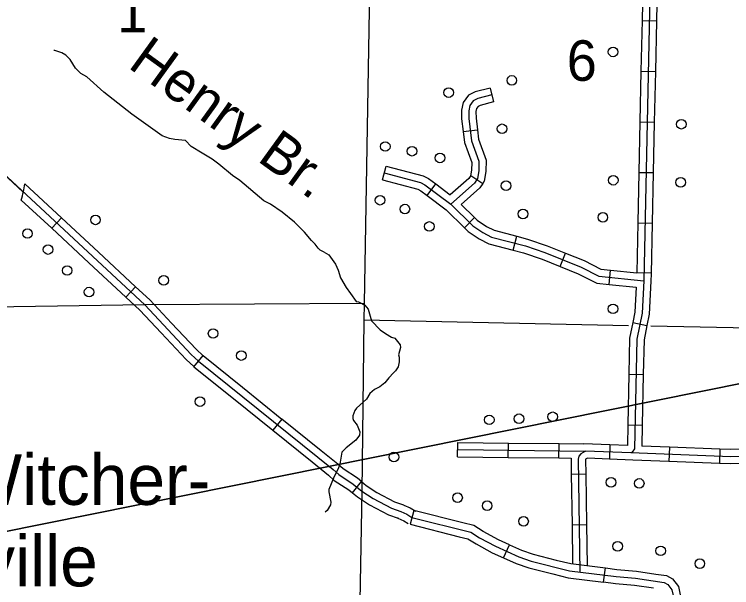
# Model space of a CAD drawing. Extents: x -4786562 to 2097152, y -862751 to 524288.
# Drawn here: x 1377442.5 to 1377649.7, y 379252.8 to 379418.5 of the extents above; entities that cross this region are included whole.
import ezdxf

# ---------------------------------------------------------------- set-up
doc = ezdxf.new("R2010")
doc.units = 0
for name, color, linetype in [('Level 24', 7, 'Continuous'), ('Level 31', 7, 'Continuous'), ('Level 32', 7, 'Continuous'), ('Level 35', 7, 'Continuous'), ('Level 5', 7, 'Continuous'), ('Level 56', 7, 'Continuous'), ('R_Draft', 7, 'Continuous')]:
    doc.layers.add(name, color=color, linetype=linetype)

msp = doc.modelspace()

# ---------------------------------------------------------------- linework, layer by layer
at = {"layer": 'Level 31'}
for p, q in [((1377456.123504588, 379359.7058142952), (1377453.2946818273, 379356.66239634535)), ((1377519.7837339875, 379301.5479141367), (1377517.1760714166, 379298.313003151)), ((1377540.1498063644, 379280.255871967), (1377542.7671917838, 379283.4829160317)), ((1377557.897883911, 379275.15342605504), (1377556.8754058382, 379271.1261167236)), ((1377583.8640403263, 379261.4316883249), (1377585.5618824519, 379265.2240426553)), ((1377612.736719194, 379254.40301028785), (1377613.2494540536, 379258.5263015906)), ((1377627.8198219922, 379256.763557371), (1377627.819849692, 379256.763557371))]:
    msp.add_line(p, q, dxfattribs=at)
for points in [[(1377390.8982565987, 379418.4212686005), (1377418.510399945, 379391.8304399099), (1377480.1879991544, 379334.5016965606), (1377493.5597697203, 379320.2058952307), (1377495.7061094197, 379318.28838873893)], [(1377390.8982565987, 379418.4212686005), (1377418.510399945, 379391.8304399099), (1377445.0951622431, 379367.12016534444)], [(1377445.5780360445, 379369.50769264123), (1377456.123504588, 379359.70578659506)], [(1377453.2946818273, 379356.66239634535), (1377444.5062235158, 379364.8311961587)], [(1377456.123504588, 379359.70578659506), (1377466.836283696, 379349.7483426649)], [(1377453.2946818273, 379356.66239634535), (1377464.0074609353, 379346.7049524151)], [(1377466.836283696, 379349.7483426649), (1377477.5490905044, 379339.79089873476)], [(1377464.0074609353, 379346.7049524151), (1377474.7202677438, 379336.7475084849)], [(1377497.0099407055, 379319.90584423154), (1377508.3968373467, 379310.72689303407)], [(1377495.7061094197, 379318.28838873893), (1377534.6056494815, 379286.9315080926), (1377536.2200579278, 379285.47593388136), (1377540.3886948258, 379282.73710980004), (1377542.8923423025, 379280.7064470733), (1377546.199218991, 379278.57052273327), (1377551.4476461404, 379275.7559656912), (1377554.1381052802, 379274.80570262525), (1377555.941984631, 379274.01543721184), (1377557.386644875, 379273.13977138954)], [(1377494.4022781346, 379316.6709332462), (1377505.7891747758, 379307.4919820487)], [(1377508.3968373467, 379310.72689303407), (1377519.7837339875, 379301.5479141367)], [(1377505.7891747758, 379307.4919820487), (1377517.1760714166, 379298.313003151)], [(1377531.170630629, 379292.3689629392), (1377519.7837339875, 379301.5479141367)], [(1377517.1760714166, 379298.313003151), (1377528.5629680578, 379289.13405195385)], [(1377542.7672194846, 379283.4829160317), (1377541.6165161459, 379284.41622643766), (1377537.4934187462, 379287.1251340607), (1377535.9541892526, 379288.5129253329), (1377531.170630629, 379292.3689629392)], [(1377528.5629680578, 379289.13405195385), (1377533.2571097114, 379285.3500908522), (1377534.9466971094, 379283.82673370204), (1377539.1608735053, 379281.05799316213), (1377540.1498063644, 379280.255871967)], [(1377542.7672194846, 379283.4829160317), (1377544.1138479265, 379282.3906882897), (1377547.2554915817, 379280.3614936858), (1377552.2894066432, 379277.66197650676), (1377554.901473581, 379276.73938616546), (1377555.0021923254, 379276.69531478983)], [(1377540.1498063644, 379280.255871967), (1377541.6708366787, 379279.02220585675), (1377545.1429464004, 379276.779551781), (1377550.6058856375, 379273.84995487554), (1377553.374736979, 379272.87201908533), (1377553.3365657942, 379272.8887224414)], [(1377555.0030510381, 379276.69495468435), (1377556.901444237, 379275.8632494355), (1377558.4635265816, 379274.91642122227)], [(1377572.0739363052, 379271.55422678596), (1377557.897883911, 379275.15342605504)], [(1377553.3357070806, 379272.88908254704), (1377554.9825250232, 379272.1676249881), (1377556.3097631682, 379271.36312155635)], [(1377557.386644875, 379273.13977138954), (1377574.3824619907, 379268.82465464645), (1377576.9349176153, 379267.2449825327), (1377581.499227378, 379264.7666532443), (1377588.28940476, 379261.72669784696), (1377591.7749214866, 379260.4995690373), (1377602.9036224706, 379257.7192774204), (1377616.3878844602, 379256.04251531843), (1377621.9602680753, 379255.55296571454), (1377630.261143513, 379254.2909897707), (1377631.2688849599, 379253.75858760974), (1377632.4643244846, 379252.23279282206), (1377632.804818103, 379250.57780325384), (1377632.050812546, 379229.3391121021), (1377632.269784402, 379228.180209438), (1377632.5626609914, 379227.4384751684), (1377633.161599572, 379226.6202046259), (1377654.8432759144, 379213.2065233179)], [(1377585.5618824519, 379265.2240426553), (1377582.4207097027, 379266.6303378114), (1377577.9780879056, 379269.04260158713), (1377575.20375188, 379270.7595847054), (1377572.0739363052, 379271.55422678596)], [(1377556.8754058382, 379271.1261167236), (1377571.051458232, 379267.5269174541)], [(1377571.051458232, 379267.5269174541), (1377573.5611721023, 379266.88972458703), (1377575.8917473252, 379265.44736347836), (1377580.5777450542, 379262.90296867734), (1377583.8640680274, 379261.4316883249)], [(1377585.5618824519, 379265.2240426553), (1377589.060141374, 379263.6578883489), (1377592.372973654, 379262.49153427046), (1377599.0814901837, 379260.8155477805)], [(1377583.8640680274, 379261.4316883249), (1377587.5186681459, 379259.7955073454), (1377591.1768693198, 379258.50760380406), (1377598.074358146, 379256.78436038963)], [(1377599.0814624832, 379260.8155477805), (1377603.2849742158, 379259.7653969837), (1377613.2494540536, 379258.5263015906)], [(1377598.0743858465, 379256.78436038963), (1377602.5222707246, 379255.67315785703), (1377612.736719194, 379254.4029825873)], [(1377613.2494540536, 379258.5263015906), (1377616.6070502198, 379258.10880079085), (1377622.2075497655, 379257.61678584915), (1377627.8198219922, 379256.763557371)], [(1377627.819849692, 379256.763557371), (1377630.9208568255, 379256.29209614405), (1377632.6310533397, 379255.3885913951), (1377634.4008334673, 379253.1297325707), (1377634.8898567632, 379250.7527591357), (1377634.6301098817, 379243.43563657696)], [(1377627.1953436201, 379252.65569520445), (1377621.7129863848, 379253.48914557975), (1377616.1687187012, 379253.97622984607), (1377612.736719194, 379254.4029825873)]]:
    msp.add_lwpolyline(points, dxfattribs=at)
msp.add_arc((1377400.3578788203, 379377.410688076), 45.90555474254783, 344.09579166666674, 350.0867027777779, dxfattribs=at)
at = {"layer": 'Level 32'}
for p, q in [((1377623.8425950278, 379416.69212499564), (1377627.9967446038, 379416.6047024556)), ((1377623.5348710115, 379402.0695417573), (1377627.6889928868, 379401.9821192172)), ((1377579.945399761, 379397.1918847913), (1377580.9800660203, 379393.16773330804)), ((1377623.227119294, 379387.44693081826), (1377627.38126887, 379387.3595082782)), ((1377572.1713309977, 379384.6481353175), (1377576.29586882, 379385.1508703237)), ((1377548.8409530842, 379370.629615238), (1377549.883707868, 379374.65171689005)), ((1377622.9193952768, 379372.82434757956), (1377627.073544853, 379372.7369250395)), ((1377574.3528225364, 379371.8831979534), (1377577.8359293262, 379369.61769102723)), ((1377561.7391571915, 379366.1518139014), (1377564.237347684, 379369.472014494)), ((1377572.5643723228, 379356.7755525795), (1377575.476324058, 379359.7395257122)), ((1377622.6116435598, 379358.20176434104), (1377626.7657931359, 379358.1143418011)), ((1377586.61798884, 379350.335314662), (1377587.6649263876, 379354.3563359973)), ((1377600.1787317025, 379345.656048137), (1377601.7271300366, 379349.5118087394)), ((1377614.3024579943, 379340.4433822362), (1377614.7420914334, 379344.57512216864)), ((1377626.4620856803, 379343.68264218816), (1377622.3079361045, 379343.7700647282)), ((1377621.1916089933, 379329.4031287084), (1377625.262463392, 379328.5707309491)), ((1377620.0624011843, 379314.4938183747), (1377624.2166338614, 379314.4116035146)), ((1377619.7729317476, 379299.87087503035), (1377623.9271921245, 379299.78863246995)), ((1377570.5774208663, 379290.630899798), (1377570.624068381, 379294.78568648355)), ((1377585.2023309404, 379290.4667193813), (1377585.2489784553, 379294.6215060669)), ((1377599.8272410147, 379290.3025389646), (1377599.873860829, 379294.45732565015)), ((1377614.5827862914, 379294.0924002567), (1377614.4173593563, 379289.9406329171)), ((1377631.7332271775, 379293.4170639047), (1377631.570791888, 379289.2651857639)), ((1377646.3478603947, 379292.84535484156), (1377646.185452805, 379288.69347670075)), ((1377603.4170775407, 379285.6075939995), (1377607.5717257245, 379285.6672330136)), ((1377603.6270467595, 379270.983265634), (1377607.7816949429, 379271.04293234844))]:
    msp.add_line(p, q, dxfattribs=at)
for points in [[(1377626.842883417, 379460.5161634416), (1377624.3374077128, 379341.46486309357), (1377623.8711541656, 379332.1370775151), (1377622.3414813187, 379324.65599614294), (1377621.7137342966, 379292.9424448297), (1377620.9448813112, 379291.99650303), (1377620.6142213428, 379291.77290520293), (1377607.5486235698, 379292.2935069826), (1377606.1698903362, 379291.50944646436), (1377605.620867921, 379290.81399960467), (1377605.4328097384, 379289.927309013), (1377605.901473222, 379257.2851286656)], [(1377624.1503467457, 379431.3147082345), (1377623.8426227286, 379416.69212499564)], [(1377628.3044686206, 379431.22728569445), (1377627.9967446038, 379416.6047024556)], [(1377623.8426227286, 379416.69212499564), (1377623.5348710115, 379402.0695417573)], [(1377627.9967446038, 379416.6047024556), (1377627.6889928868, 379401.9821192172)], [(1377623.5348710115, 379402.0695417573), (1377623.2271469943, 379387.44693081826)], [(1377627.6889928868, 379401.9821192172), (1377627.38126887, 379387.3595082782)], [(1377579.945399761, 379397.1918847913), (1377575.6355183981, 379396.08375700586), (1377573.7392304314, 379395.11992073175), (1377572.1418023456, 379393.0197299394), (1377571.7158252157, 379390.81715837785), (1377571.7322238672, 379388.25079713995), (1377572.1713309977, 379384.6481353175)], [(1377580.4627328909, 379395.1798090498), (1377576.373651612, 379394.1284394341), (1377575.1047505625, 379393.4834904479), (1377574.089336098, 379392.148496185), (1377573.7946312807, 379390.6246958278), (1377573.8089524, 379388.38353757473), (1377574.5974726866, 379381.9141865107), (1377576.710738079, 379376.0071817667), (1377576.6727053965, 379373.2953101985), (1377576.2721018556, 379371.0236814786), (1377575.4225298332, 379369.71749565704), (1377568.5706082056, 379363.6116295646)], [(1377580.9800660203, 379393.16773330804), (1377577.1117848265, 379392.17312186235), (1377576.470270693, 379391.8470601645), (1377576.03686985, 379391.2772624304), (1377575.8734373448, 379390.4322332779), (1377575.8856809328, 379388.51627800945), (1377576.29586882, 379385.1508426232)], [(1377623.2271469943, 379387.44693081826), (1377622.9193952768, 379372.82434757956)], [(1377627.38126887, 379387.3595082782), (1377627.073517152, 379372.7369250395)], [(1377572.1713309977, 379384.6481353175), (1377572.5632643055, 379381.43267003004), (1377574.6281370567, 379375.6608987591), (1377574.597721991, 379373.4915400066), (1377574.2996931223, 379371.8015094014), (1377574.3528502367, 379371.8832256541)], [(1377576.29586882, 379385.1508426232), (1377576.6316810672, 379382.3957029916), (1377578.793339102, 379376.3534647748), (1377578.747688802, 379373.0990803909), (1377578.2445105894, 379370.24585355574), (1377577.835901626, 379369.61766332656)], [(1377549.883707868, 379374.65171689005), (1377560.6410015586, 379371.86281044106), (1377562.1929178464, 379371.01030217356), (1377564.237347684, 379369.472014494)], [(1377622.9193952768, 379372.82434757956), (1377622.61167126, 379358.20176434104)], [(1377549.3623304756, 379372.6406660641), (1377559.8682982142, 379369.91691101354), (1377561.0624912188, 379369.2609095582), (1377568.5706082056, 379363.6116295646), (1377574.9201826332, 379357.37349394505), (1377577.8109158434, 379355.40078050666), (1377580.3374715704, 379354.1173644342), (1377590.178213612, 379351.55515826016), (1377595.725029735, 379349.6833574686), (1377606.2960657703, 379345.4382396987), (1377611.3770161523, 379342.8439287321), (1377624.3374077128, 379341.46486309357)], [(1377574.3528225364, 379371.8831702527), (1377573.8326639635, 379371.08345899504), (1377568.4593910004, 379366.29524669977)], [(1377627.073517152, 379372.7369250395), (1377626.7657931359, 379358.1143418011)], [(1377548.8409530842, 379370.629615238), (1377559.09559487, 379367.97101158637), (1377559.9320645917, 379367.5115169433), (1377561.7391571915, 379366.15184160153)], [(1377564.237347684, 379369.472014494), (1377568.4593910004, 379366.29524669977)], [(1377577.8359293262, 379369.61771872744), (1377577.0123957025, 379368.35153231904), (1377571.6103419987, 379363.53764173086)], [(1377561.7391571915, 379366.15184160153), (1377567.2122070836, 379362.03378567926), (1377572.5643446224, 379356.7755525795)], [(1377571.6103419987, 379363.53764173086), (1377575.476324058, 379359.73949801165)], [(1377575.4762963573, 379359.7395257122), (1377576.2441244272, 379358.98518774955), (1377578.8712880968, 379357.19233316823), (1377581.078208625, 379356.0712969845), (1377587.6649263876, 379354.3563359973)], [(1377572.5643723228, 379356.7755248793), (1377573.5962408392, 379355.76180014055), (1377576.7505435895, 379353.60922784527), (1377579.5967345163, 379352.1634318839), (1377586.6180165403, 379350.3353423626)], [(1377622.61167126, 379358.20176434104), (1377622.3079361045, 379343.7700647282)], [(1377626.7657931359, 379358.1143418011), (1377626.4580414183, 379343.4917585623)], [(1377587.664954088, 379354.3563359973), (1377590.7728309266, 379353.5471234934), (1377596.4448252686, 379351.63307955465), (1377601.7271300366, 379349.51183643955)], [(1377586.61798884, 379350.3353423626), (1377589.5835962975, 379349.563193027), (1377595.0052342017, 379347.73363538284), (1377600.1787317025, 379345.656048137)], [(1377601.7271300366, 379349.51183643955), (1377607.1572996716, 379347.331175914), (1377611.9792510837, 379344.86910677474), (1377614.7420914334, 379344.57512216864)], [(1377600.1787317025, 379345.656048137), (1377605.4348318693, 379343.54530348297), (1377610.7747812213, 379340.8187506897), (1377614.3024302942, 379340.4433822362)], [(1377614.7420914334, 379344.57512216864), (1377622.3079361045, 379343.7700647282)], [(1377626.4580414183, 379343.4917585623), (1377626.4138592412, 379341.3911245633), (1377625.9382152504, 379331.87561320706), (1377625.262463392, 379328.5707309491)], [(1377614.3024302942, 379340.4433822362), (1377622.164392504, 379339.6068294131)], [(1377622.164392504, 379339.6068294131), (1377621.8040930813, 379332.3985418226), (1377621.1916089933, 379329.4031287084)], [(1377621.1916089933, 379329.4031287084), (1377620.2681045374, 379324.8865467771), (1377620.0624011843, 379314.4938183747)], [(1377625.262463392, 379328.5707309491), (1377624.4148581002, 379324.42544550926), (1377624.2166338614, 379314.4116035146)], [(1377620.0624011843, 379314.4938183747), (1377619.7729594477, 379299.87087503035)], [(1377624.2166338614, 379314.4116035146), (1377623.9271921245, 379299.7886601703)], [(1377619.7729594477, 379299.87087503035), (1377619.6545678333, 379293.890325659), (1377614.5827862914, 379294.0924279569)], [(1377623.9271921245, 379299.7886601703), (1377623.8071938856, 379293.72675465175)], [(1377570.624068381, 379294.78568648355), (1377585.2489784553, 379294.6215060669)], [(1377585.2489784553, 379294.6215060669), (1377599.873860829, 379294.45732565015)], [(1377599.873860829, 379294.45732565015), (1377607.0378831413, 379294.39303296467)], [(1377614.5827862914, 379294.0924279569), (1377607.0378831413, 379294.39303296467)], [(1377570.600744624, 379292.7082931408), (1377607.5486235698, 379292.2935069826)], [(1377631.7330055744, 379293.4170639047), (1377623.8071938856, 379293.72675465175)], [(1377646.3478603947, 379292.84538254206), (1377631.7332271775, 379293.4170639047)], [(1377661.1410782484, 379291.28271848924), (1377658.3185711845, 379291.8410759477), (1377655.4176996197, 379292.53128742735), (1377653.012083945, 379292.8271833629), (1377649.5436583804, 379292.7203428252), (1377646.3478603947, 379292.84538254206)], [(1377570.5774208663, 379290.630899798), (1377585.2023309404, 379290.4667193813)], [(1377585.2023309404, 379290.4667193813), (1377599.8272133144, 379290.3025389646)], [(1377599.8365760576, 379290.302428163), (1377603.3501256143, 379290.27090507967)], [(1377603.3805683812, 379290.26445088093), (1377603.3521477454, 379290.1304362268), (1377603.417105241, 379285.6075939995)], [(1377614.4173593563, 379289.9406329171), (1377608.0593639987, 379290.1939810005), (1377607.5519199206, 379289.9053979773), (1377607.513471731, 379289.7241817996), (1377607.5717257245, 379285.66726071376)], [(1377621.2129937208, 379289.66986126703), (1377614.4173593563, 379289.9406329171)], [(1377698.5888667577, 379274.3839913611), (1377696.4273195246, 379281.0505694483), (1377695.2861728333, 379282.0666487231), (1377694.397266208, 379282.5863917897), (1377657.8763893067, 379289.8107456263), (1377655.049311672, 379290.48342273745), (1377652.9167113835, 379290.7457180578), (1377649.535015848, 379290.6415644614), (1377620.6142213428, 379291.77290520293)], [(1377631.570791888, 379289.2651580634), (1377621.2129937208, 379289.66986126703)], [(1377646.1854251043, 379288.69347670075), (1377631.570791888, 379289.2651580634)], [(1377660.3347742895, 379287.2066564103), (1377657.4342074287, 379287.7804153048), (1377654.680923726, 379288.43555804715), (1377652.8213388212, 379288.6642527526), (1377649.5263733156, 379288.56278609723), (1377646.1854251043, 379288.69347670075)], [(1377603.417105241, 379285.6075939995), (1377603.6270744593, 379270.983265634)], [(1377607.5717257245, 379285.66726071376), (1377607.7816949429, 379271.04293234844)], [(1377603.6270744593, 379270.983265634), (1377603.7890388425, 379259.7027109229)], [(1377607.7816949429, 379271.04293234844), (1377607.951941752, 379259.1850453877)]]:
    msp.add_lwpolyline(points, dxfattribs=at)
at = {"layer": 'Level 35'}
for points in [[(1377532.0179312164, 379349.80692906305), (1377530.8790282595, 379350.35941403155), (1377530.2383728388, 379350.879351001), (1377529.4540353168, 379352.03451410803), (1377528.3103124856, 379353.158652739), (1377526.3541639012, 379355.49307832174), (1377523.3967557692, 379358.4547800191), (1377519.8865025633, 379361.3560393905), (1377516.464115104, 379363.67686406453), (1377514.603200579, 379364.5453000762), (1377507.609480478, 379370.45873131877), (1377505.5502586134, 379371.8788489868), (1377501.5660511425, 379375.218522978), (1377499.7007322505, 379376.61276844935), (1377496.8090572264, 379378.32961306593), (1377493.5835643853, 379380.26482012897), (1377491.9642252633, 379382.02113785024), (1377488.9183419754, 379382.32503920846), (1377487.3389191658, 379382.61486875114), (1377485.2576200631, 379383.37053633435), (1377476.4352564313, 379389.5991707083), (1377468.3312479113, 379395.94514408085), (1377463.452510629, 379400.3836108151), (1377461.7010958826, 379401.39143536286), (1377460.1386811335, 379402.9545426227), (1377458.6516669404, 379405.43168079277), (1377457.396588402, 379406.63784038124), (1377456.2010103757, 379407.3463618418), (1377454.2036158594, 379407.99211413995), (1377453.8714046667, 379408.016712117)], [(1377532.0179312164, 379349.80692906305), (1377533.3237015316, 379349.0133395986), (1377535.3338382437, 379346.25994509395), (1377536.0919711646, 379344.54955467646), (1377536.7704376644, 379342.3128838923), (1377538.3931285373, 379339.5568855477), (1377539.6220578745, 379337.79433523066), (1377541.2415908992, 379335.5363351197), (1377541.9064564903, 379335.4301593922), (1377543.7667339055, 379334.47427314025), (1377544.687357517, 379333.318362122), (1377545.7053204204, 379329.92187455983), (1377548.2125135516, 379327.3378404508), (1377549.6862592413, 379326.24101443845), (1377551.4362058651, 379325.2290348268), (1377552.4623957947, 379324.87626991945), (1377553.9414322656, 379322.94937298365), (1377554.056721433, 379322.230740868), (1377553.489001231, 379320.12404047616), (1377553.6319631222, 379319.4055745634), (1377553.6959788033, 379318.05022048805), (1377553.373074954, 379316.60921670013), (1377552.6329750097, 379315.4974324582), (1377552.0282193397, 379314.85697094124), (1377550.6808983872, 379313.49206021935), (1377549.5554855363, 379312.0456548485), (1377548.0962271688, 379310.8736775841), (1377546.523978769, 379310.06067012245), (1377545.175078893, 379308.9447862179), (1377544.2172813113, 379307.2504897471), (1377541.355522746, 379304.6855689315), (1377540.8893245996, 379304.0183488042), (1377540.2902198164, 379302.4924986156), (1377540.2673392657, 379301.7452519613), (1377540.492959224, 379301.0827132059), (1377541.5806717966, 379299.76190156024), (1377542.3400512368, 379297.85782977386), (1377542.2633764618, 379296.86122389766), (1377541.1929766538, 379295.4705240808), (1377538.3847907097, 379293.18266291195), (1377537.119767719, 379291.92899709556), (1377536.5325187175, 379288.5493513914)], [(1377536.5325187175, 379288.5493513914), (1377536.043052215, 379287.19025775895), (1377534.8674184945, 379284.94109408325), (1377533.3690748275, 379281.2232538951), (1377533.3179675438, 379280.55883151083), (1377533.973885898, 379277.51962402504), (1377533.8677932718, 379276.7994960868), (1377532.8823229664, 379275.10500571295), (1377532.3320540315, 379274.6032402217)]]:
    msp.add_lwpolyline(points, dxfattribs=at)
at = {"layer": 'Level 5'}
for p, q in [((1377477.5490905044, 379339.7909264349), (1377474.7202677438, 379336.7475084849)), ((1377494.4022781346, 379316.6709332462), (1377497.0099407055, 379319.90584423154))]:
    msp.add_line(p, q, dxfattribs=at)
for points in [[(1377546.178222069, 379490.23520108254), (1377546.0895530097, 379482.13462741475), (1377543.5975120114, 379334.9711910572), (1377543.490228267, 379330.1006253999), (1377542.8923423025, 379280.7064470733), (1377541.3419772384, 379196.0190746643)], [(1377487.9160852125, 379329.2808590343), (1377481.6556230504, 379335.9739464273), (1377477.5490905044, 379339.79089873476)], [(1377474.7202677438, 379336.7475084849), (1377478.7203752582, 379333.0294466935), (1377484.8815590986, 379326.44250732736)], [(1377543.5975120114, 379334.9711910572), (1377480.1879991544, 379334.5016965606), (1377435.9049923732, 379333.90533411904)], [(1377497.0902442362, 379319.83770118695), (1377495.0133772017, 379321.6931310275), (1377487.9160852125, 379329.2808590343)], [(1377619.8995780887, 379328.49355756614), (1377543.490228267, 379330.1006253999)], [(1377755.4088132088, 379326.1137871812), (1377697.6287700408, 379326.9347992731), (1377626.4098703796, 379328.35993071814)], [(1377484.8815590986, 379326.44250732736), (1377492.1061622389, 379318.7186594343), (1377494.3219746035, 379316.73907629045)]]:
    msp.add_lwpolyline(points, dxfattribs=at)
at = {"layer": 'Level 56'}
for centre, radius in [((1377615.47518317, 379407.6110116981), 1.3850212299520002), ((1377586.23505817, 379399.38708803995), 1.3850228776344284), ((1377567.9680685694, 379395.8653391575), 1.3850195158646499), ((1377635.1992428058, 379386.7290189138), 1.3850205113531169), ((1377583.4087838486, 379385.418179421), 1.3850185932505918), ((1377549.6635171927, 379380.2864264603), 1.3850220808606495), ((1377557.397226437, 379378.92242985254), 1.3850220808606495), ((1377565.469517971, 379376.9882477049), 1.3850204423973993), ((1377615.5315812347, 379370.53150033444), 1.3850205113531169), ((1377635.01099072, 379369.9294593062), 1.3850212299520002), ((1377584.5649164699, 379368.9673127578), 1.3850223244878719), ((1377548.164481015, 379364.7709200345), 1.3850220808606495), ((1377555.3283094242, 379362.21073599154), 1.3850220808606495), ((1377465.9534988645, 379359.0818068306), 1.385020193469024), ((1377589.4454542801, 379360.79142163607), 1.3850218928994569), ((1377612.5281349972, 379359.8239289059), 1.3850212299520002), ((1377562.4021114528, 379357.19382899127), 1.385017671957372), ((1377446.304424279, 379355.1425848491), 1.385020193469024), ((1377452.2514007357, 379350.50711269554), 1.385020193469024), ((1377457.7709042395, 379344.45961139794), 1.385020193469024), ((1377485.6612152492, 379341.6108720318), 1.3850208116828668), ((1377464.0958529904, 379338.2336362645), 1.3850214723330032), ((1377615.461526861, 379333.3923499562), 1.3850190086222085), ((1377499.9266846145, 379326.2680777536), 1.3850208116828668), ((1377508.067257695, 379319.8875342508), 1.3850208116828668), ((1377496.127765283, 379306.583408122), 1.3850208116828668), ((1377579.7064281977, 379301.3099397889), 1.3850205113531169), ((1377588.3069945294, 379301.63143091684), 1.3850205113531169), ((1377598.0261317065, 379302.19649187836), 1.3850205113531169), ((1377552.1640899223, 379290.5701804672), 1.3850222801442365), ((1377614.883779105, 379283.2455510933), 1.3850205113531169), ((1377623.0306124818, 379282.94635880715), 1.3850205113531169), ((1377570.5445404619, 379278.82392621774), 1.3850200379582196), ((1377579.1022819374, 379276.5152343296), 1.3850212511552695), ((1377589.6172800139, 379271.9981537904), 1.3850264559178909), ((1377616.788349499, 379264.76720725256), 1.3850268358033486), ((1377629.2293857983, 379263.46013501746), 1.385026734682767), ((1377640.5454524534, 379259.76320865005), 1.3850205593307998)]:
    msp.add_circle(centre, radius, dxfattribs=at)
at = {"layer": 'R_Draft'}
msp.add_ellipse((1377399.5771814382, 379095.1231578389), major_axis=(-7.799978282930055, 173.0873096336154), ratio=0.4401192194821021, dxfattribs=at)
msp.add_spline([(1378537.1312526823, 379490.139278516), (1378537.1310216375, 379490.1335409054), (1378537.1305980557, 379490.13469612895), (1378537.1308676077, 379490.1295746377), (1378537.1308676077, 379490.1295746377), (1378537.130713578, 379490.1301522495), (1378537.1312141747, 379490.12449165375)], degree=3, dxfattribs=at)

# ---------------------------------------------------------------- texts
at = {"layer": 'Level 24'}
for s, p in [('Witcher-', (1377426.2876265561, 379276.7471145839)), ('ville', (1377432.9321274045, 379253.20599183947))]:
    msp.add_text(s, height=14.62582418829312, dxfattribs=at).set_placement(p)
at = {"layer": 'Level 35'}
msp.add_text('Henry Br.', height=11.700659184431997, rotation=324.1576527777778, dxfattribs=at).set_placement((1377474.9909285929, 379403.3151467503))
at = {"layer": 'Level 5'}
for s, p in [('1', (1377472.1924654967, 379413.23034753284)), ('6', (1377602.0926094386, 379399.26310093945))]:
    msp.add_text(s, height=11.700659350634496, dxfattribs=at).set_placement(p)

doc.saveas('drawing.dxf')
